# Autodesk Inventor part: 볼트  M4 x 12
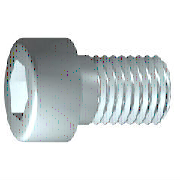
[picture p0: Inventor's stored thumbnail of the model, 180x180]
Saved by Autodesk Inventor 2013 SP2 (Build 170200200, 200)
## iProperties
IsCustomPart: 0
Created: 2015-12
Part Number: 볼트  M4 x 12
Material: 일반
Description: 6각머리 태핑 나사
Document SubType Name: Modeling
Standard: KS B 1003
Designer: mdu
Standards Organization: KS
Language: ko-KR
Size Designation: M 4 x 12
Categories: <MemberInstance><Categories><Category DisplayName="조임쇠" InternalName="e4da775c-781d-43d5-af7c-5136215cf5a6" Mnemonic="FSTN"><Category DisplayName="볼트" InternalN
Density: 1 g/cm^3
Mass: 0.284306 g
Surface Area: 3.30853 cm^2
Volume: 0.284306 cm^3
Author: mdu
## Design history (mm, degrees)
sketch "스케치1"
  geometry: L1 (-1, 0)-(12, 0); L2 (12, 0)-(12, 2); L3 (12, 2)-(1.75, 2); L4 (1.75, 2)-(1.32, 2); L5 (1.32, 2)-(0, 2); L6 (0, 2)-(0, 3.5); L7 (0, 3.5)-(-4, 3.5); L8 (-4, 3.5)-(-4, 1.732); L9 (-4, 1.732)-(-2, 1.732); L10 (-2, 1.732)-(-1, 0); L11 (-7.2, 0)-(15.2, 0) reference; L12 (0, -0.7)-(0, 4.2) reference; L13 (1.75, 2)-(0, 2)
  constraints: 22 end point, 6 parallel, 2 collinear, 2 perpendicular, 1 horizontal, 1 point on line
  dimensions: "d1" = 10.25 distance from line of L3.end L2 (= GEL); "d2" = 0.42952 distance of L4.end L3.end (computed from GAL); "d3" = 4 distance between parallel lines of L8 L6 (= KOH); "d4" = 2 distance of L8.end L9.end (= INTI); "d5" = 60 deg angle of L10 L1; "d6" = 4 diameter of L3 L1 (= GD); "d7" = 4 diameter of L5 L1 (= BDM); "d8" = 3.4641 diameter of L9 L1 (= 1.1547 x SW); "d9" = 7 diameter of L7 L1 (= KOD); "d26" = 12 distance between parallel lines of L12 L2 (= NLG)
revolve "본체" sketch "스케치1" stored, may be unused: angle "d10" = 90 deg
sketch "스케치2"
  geometry: L1 (0, -4.9)-(0, 4.9) reference; L2 (-4.9, 0)-(4.9, 0) reference; L3 (1.732, 0)-(0.866, -1.5); L4 (0.866, -1.5)-(-0.866, -1.5); L5 (-0.866, -1.5)-(-1.732, 0); L6 (-1.732, 0)-(-0.866, 1.5); L7 (-0.866, 1.5)-(0.866, 1.5); L8 (0.866, 1.5)-(1.732, 0); 2 further points
  constraints: 12 end point, 1 coincident, 1 horizontal alignment, 1 point on line, 12 other
extrude "슬롯" join sketch "스케치2" stored distance "d11" = 10; taper "d12" = 0 deg
workplane "Work Plane1"
fillet "Fillet2" dims "d30" = 0.1 (= R)
body "Solid1"
fillet "모깎기1" dims "d17" = 0.4 (= RR)
feature "스레드" dims "d13" = 10.25 (= GEL), "d14" = 0
chamfer "모따기1" distance "d15" = 0.42941 (= -0.5 x SPD + 0.5 x GD); stored, may be unused: second distance "d16" = 0.42941 (= GUL), angle "d27" = 45 deg
other parameters: "GD" = 4 (= NND) [user parameter; used in 2 equation terms], "NLG" = 12 [user parameter; used in 1 equation term], "GEL" = 10.25 [user parameter; used in 2 equation terms], "KOD" = 7 [user parameter; used in 1 equation term], "KOH" = 4 [user parameter; used in 1 equation term], "INTI" = 2 [user parameter; used in 1 equation term], "GAL" = 0.42941 (= 0.61345 x PTC) [user parameter; used in 1 equation term], "GUL" = 0.42941 (= 0.61345 x PTC) [user parameter; used in 1 equation term], "BDM" = 4 (= NND) [user parameter; used in 1 equation term], "SW" = 3 [user parameter; used in 2 equation terms], "RR" = 0.4 [user parameter; used in 1 equation term], "SPD" = 3.14117 (= NND - 1.2269 x PTC) [user parameter; used in 1 equation term], "d19" = 0, "d28" = 0, "d29" = 0, "R" = 0.1 [user parameter; used in 1 equation term], "PHH" = 0.2 [user parameter], "GD1" = 3.14117 (= THREADDIA - 1.2269 x PTC) [user parameter], "THREADDIA" = 4 [user parameter; used in 1 equation term], "FAWI" = 45 deg [user parameter], "TPU" = 14.28571 (computed from PTC) [user parameter], "PTC" = 0.7 [user parameter; used in 5 equation terms], "NND" = 4 [user parameter; used in 3 equation terms], "TOA" = 30 deg [user parameter], "E0" = 3.465 (= 1.155 x SW) [user parameter]
